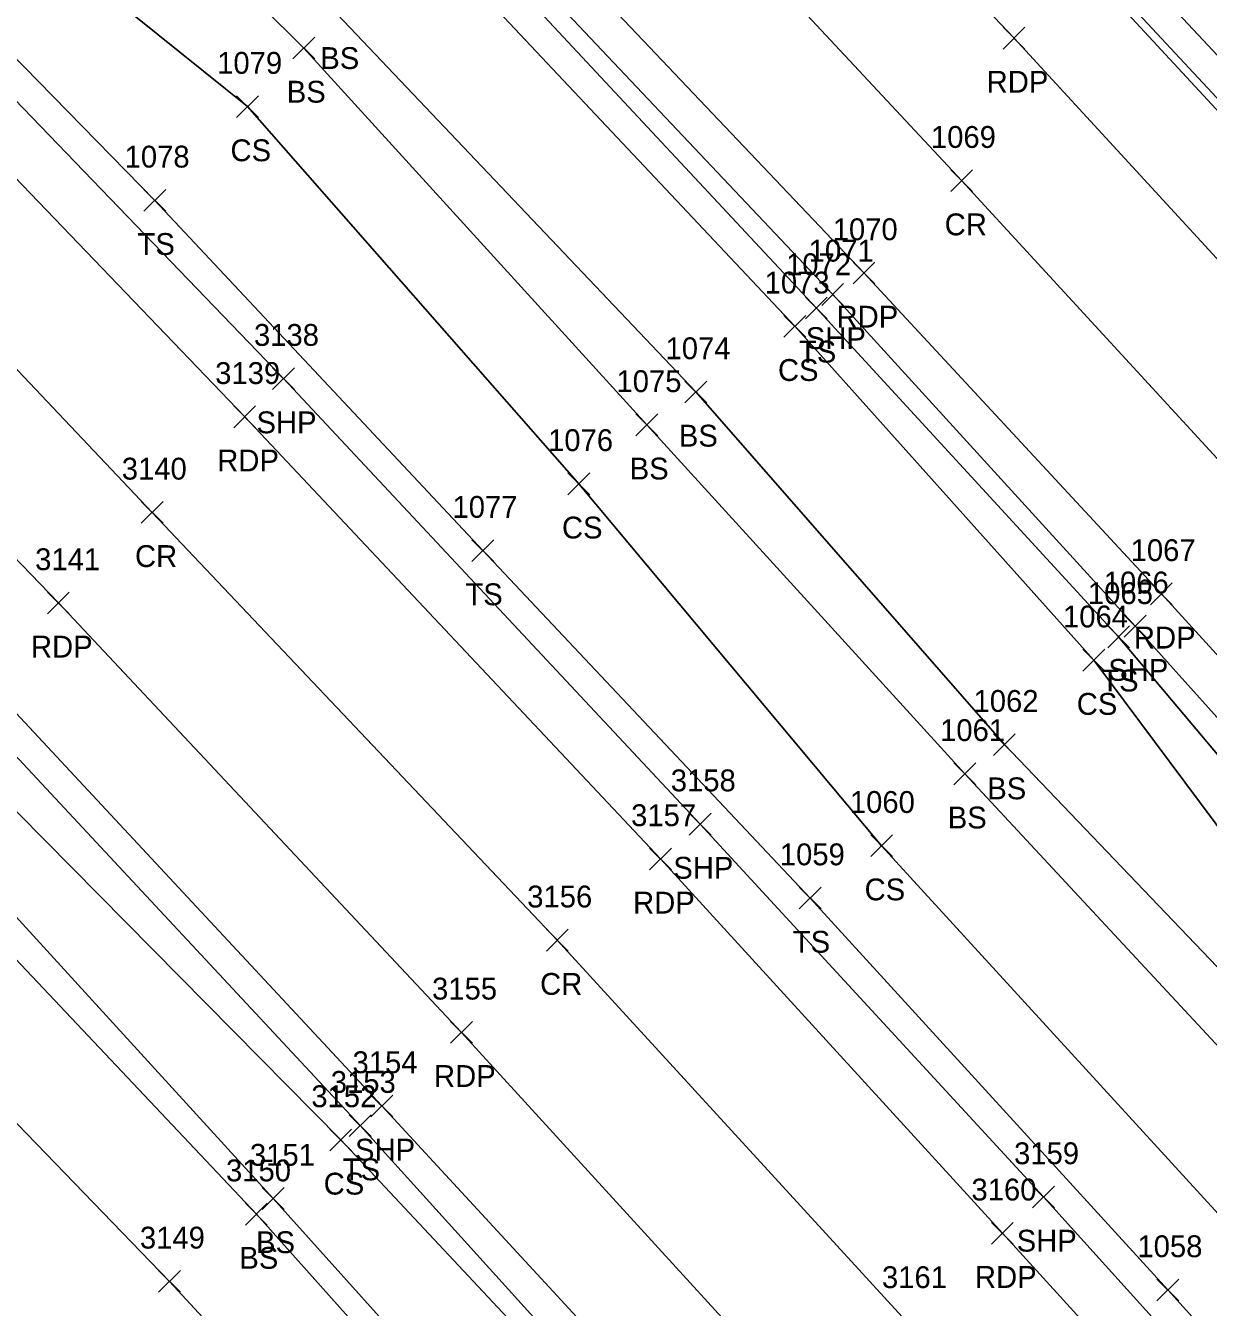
# Model space of a CAD drawing. Extents: x 1647574 to 1652703, y 212895 to 228670.
# Drawn here: x 1649906.5 to 1650014.7, y 226147.3 to 226264.6 of the extents above; entities that cross this region are included whole.
import ezdxf

# ---------------------------------------------------------------- set-up
doc = ezdxf.new("R2010")
doc.units = 0
for name, color, linetype in [('L_A', 7, 'Continuous'), ('L_I', 7, 'Continuous'), ('L_TIC', 7, 'Continuous'), ('LAWA', 7, 'Continuous'), ('LELB', 7, 'Continuous'), ('P_A', 7, 'Continuous'), ('P_I', 7, 'Continuous'), ('P_TIC', 7, 'Continuous'), ('PET', 7, 'Continuous'), ('PRC', 7, 'Continuous'), ('PSP', 7, 'Continuous'), ('RGR', 7, 'Continuous')]:
    doc.layers.add(name, color=color, linetype=linetype)

msp = doc.modelspace()

# ---------------------------------------------------------------- linework, layer by layer
at = {"layer": 'L_TIC'}
for points in [[(1649930.94, 226261.56), (1649932.94, 226263.56)], [(1649932.94, 226261.56), (1649930.94, 226263.56)], [(1649925.78, 226256.2), (1649927.78, 226258.2)], [(1649927.78, 226256.2), (1649925.78, 226258.2)], [(1649917.31, 226247.62), (1649919.31, 226249.62)], [(1649919.31, 226247.62), (1649917.31, 226249.62)], [(1649977.85, 226237.77), (1649979.85, 226239.77)], [(1649979.85, 226237.77), (1649977.85, 226239.77)], [(1649975.89, 226236.09), (1649977.89, 226238.09)], [(1649977.89, 226236.09), (1649975.89, 226238.09)], [(1649966.82, 226230.08), (1649968.82, 226232.08)], [(1649968.82, 226230.08), (1649966.82, 226232.08)], [(1649962.33, 226227.07), (1649964.33, 226229.07)], [(1649964.33, 226227.07), (1649962.33, 226229.07)], [(1649956.12, 226221.67), (1649958.12, 226223.67)], [(1649958.12, 226221.67), (1649956.12, 226223.67)], [(1649947.32, 226215.56), (1649949.32, 226217.56)], [(1649949.32, 226215.56), (1649947.32, 226217.56)], [(1650005.52, 226207.67), (1650007.52, 226209.67)], [(1650007.52, 226207.67), (1650005.52, 226209.67)], [(1650003.25, 226205.53), (1650005.25, 226207.53)], [(1650005.25, 226205.53), (1650003.25, 226207.53)], [(1649995.06, 226197.8), (1649997.06, 226199.8)], [(1649997.06, 226197.8), (1649995.06, 226199.8)], [(1649991.44, 226195.13), (1649993.44, 226197.13)], [(1649993.44, 226195.13), (1649991.44, 226197.13)], [(1649983.83, 226188.55), (1649985.83, 226190.55)], [(1649985.83, 226188.55), (1649983.83, 226190.55)], [(1649977.29, 226183.76), (1649979.29, 226185.76)], [(1649979.29, 226183.76), (1649977.29, 226185.76)], [(1649936.1, 226162.93), (1649938.1, 226164.93)], [(1649938.1, 226162.93), (1649936.1, 226164.93)], [(1649934.32, 226161.62), (1649936.32, 226163.62)], [(1649936.32, 226161.62), (1649934.32, 226163.62)], [(1649928.13, 226156.26), (1649930.13, 226158.26)], [(1649930.13, 226156.26), (1649928.13, 226158.26)], [(1649926.6, 226154.83), (1649928.6, 226156.83)], [(1649928.6, 226154.83), (1649926.6, 226156.83)], [(1649918.64, 226148.68), (1649920.64, 226150.68)], [(1649920.64, 226148.68), (1649918.64, 226150.68)], [(1650010.02, 226147.89), (1650012.02, 226149.89)], [(1650012.02, 226147.89), (1650010.02, 226149.89)]]:
    msp.add_lwpolyline(points, dxfattribs=at)
at = {"layer": 'LAWA'}
msp.add_lwpolyline([(1649564.01, 226501.21), (1649600.78, 226471.1), (1649629.15, 226441.1), (1649657.11, 226422.45), (1649662.3, 226420.26), (1649668.81, 226414.71), (1649676.02, 226404.08), (1649707.48, 226367.52), (1649746.55, 226330.39), (1649779.45, 226297), (1649815.18, 226260.26), (1649850.99, 226223.94), (1649889.13, 226181.22), (1649919.64, 226149.68), (1649954.03, 226112.54), (1649976.77, 226080.57), (1650010.23, 226040.33), (1650031.5, 226013.99), (1650047.73, 225988.88)], dxfattribs=at)
at = {"layer": 'LELB'}
for points in [[(1650213.15, 226037.1), (1650185.87, 226070.33), (1650156.97, 226103.72), (1650126.82, 226139.03), (1650097.45, 226172.49), (1650065.12, 226208.19), (1650039.15, 226236.7), (1650005.62, 226272.51), (1649977.06, 226302.34), (1649946.85, 226333.69), (1649915.81, 226365.02), (1649884.88, 226395.87), (1649852.74, 226426.8), (1649817.4, 226461.44), (1649778.8, 226498.35), (1649747.79, 226526.99), (1649716.78, 226556.99), (1649685.05, 226589.65), (1649647.22, 226623.29), (1649611.68, 226660.43), (1649573.8, 226694.76)], [(1650145.31, 225996.12), (1650155.22, 226000.73), (1650160.97, 226007.39), (1650165.06, 226014.73), (1650162.63, 226023.17), (1650152.14, 226036.38), (1650125.52, 226068.74), (1650101.36, 226098.15), (1650073.79, 226131.47), (1650039.14, 226169.85), (1650006.52, 226208.67), (1649978.85, 226238.77), (1649944.11, 226276), (1649910.77, 226309.61), (1649879.19, 226341.22), (1649849.26, 226371.24), (1649815.2, 226404.44), (1649786.47, 226431.97), (1649749.39, 226466.79), (1649718.31, 226495.58), (1649694.54, 226518.32), (1649659.53, 226550.77), (1649625.91, 226582.74), (1649593.12, 226613.01)], [(1650145.31, 225996.12), (1650126.11, 226017.39), (1650101.66, 226047.08), (1650074.02, 226078.27), (1650048.35, 226107.52), (1650011.02, 226148.89), (1649978.29, 226184.76), (1649948.32, 226216.56), (1649918.31, 226248.62), (1649881.09, 226286.67), (1649854.51, 226315.1), (1649822.53, 226345.57), (1649790.94, 226377.4), (1649759.46, 226406.66), (1649722.98, 226440.72), (1649699.36, 226464.18), (1649670.41, 226492.35), (1649633.05, 226526.99), (1649601.72, 226556.3), (1649565.56, 226590.44)], [(1649576.43, 226518.4), (1649614.41, 226482.98), (1649642.41, 226455.9), (1649685.38, 226415.67), (1649721.92, 226380.74), (1649759.16, 226344.82), (1649794.41, 226310.27), (1649829.09, 226276.12), (1649866.9, 226238.21), (1649900.81, 226202.84), (1649937.1, 226163.93), (1649969.44, 226128.19), (1649998.01, 226097.17), (1650029.45, 226060.68), (1650045.36, 226034.05), (1650069.99, 226009.77), (1650092.51, 225984.63), (1650111.94, 225960.02)], [(1649572.06, 226513.32), (1649610.08, 226478.23), (1649638.08, 226450.58), (1649682.17, 226412.39), (1649718, 226377.59), (1649756, 226340.45), (1649789.26, 226306.39), (1649824.84, 226270.98), (1649865.01, 226237.13), (1649898.41, 226199.96), (1649935.32, 226162.62), (1649968.54, 226127.19), (1649995.98, 226095.51), (1650026.38, 226057.31)], [(1649570.19, 226510.51), (1649608.23, 226476.35), (1649636.57, 226449.06), (1649663.19, 226421.28), (1649670.48, 226414.78), (1649679.22, 226408.18), (1649715.79, 226375.57), (1649754.34, 226338.61), (1649788.1, 226305.21), (1649822.67, 226268.96), (1649860.5, 226231.77), (1649895.97, 226193.57), (1649929.13, 226157.26), (1649962.02, 226120.66), (1649988.9, 226089.08), (1650019.8, 226051.49), (1650041.89, 226022.86), (1650059.37, 225999.62), (1650079.66, 225974.03), (1650096.25, 225946.36)], [(1650034.79, 226165.59), (1650004.25, 226206.53), (1649976.89, 226237.09), (1649942.39, 226273.76), (1649905.43, 226305.34), (1649874.8, 226336.52), (1649843.44, 226365.42), (1649812.48, 226401.05), (1649784.9, 226430.14), (1649744.52, 226461.95), (1649720.63, 226485.58), (1649711.56, 226477.85), (1649711.58, 226477.78), (1649705.42, 226471.73), (1649700.93, 226467.69), (1649709.73, 226458.24)], [(1650148.97, 226010.88), (1650139.27, 226026.59), (1650113.43, 226057), (1650088.3, 226087.98), (1650061.28, 226120.08), (1650026.24, 226159.75), (1649992.44, 226196.13), (1649963.33, 226228.07), (1649931.94, 226262.56), (1649896.29, 226297.95), (1649867.38, 226328.16), (1649836.11, 226358.29), (1649802.88, 226390.85), (1649773.49, 226418.93), (1649757.57, 226433.02), (1649733.38, 226449.67), (1649721.38, 226464.7), (1649717.89, 226468.09), (1649721.1, 226472.27), (1649725.43, 226467.47)], [(1650148.97, 226010.88), (1650154.49, 226019.63), (1650146.18, 226030.47), (1650117.14, 226060.39), (1650092.92, 226091.65), (1650065.04, 226122.85), (1650030.31, 226163.04), (1649996.06, 226198.8), (1649967.82, 226231.08), (1649935.01, 226265.64), (1649900.92, 226301.66), (1649869, 226330.3), (1649837.58, 226359.92), (1649804, 226392.67), (1649775.11, 226420.09), (1649758.52, 226434.35), (1649738.4, 226455.19), (1649725.43, 226467.47)], [(1650055.12, 226113.82), (1650017.96, 226153.32), (1649984.83, 226189.55), (1649957.12, 226222.67), (1649926.78, 226257.2), (1649885.72, 226290.18), (1649859.03, 226319.45), (1649828.58, 226351.31), (1649795.6, 226382.64), (1649764.56, 226410.62), (1649728.45, 226444.97), (1649709.73, 226458.24)], [(1649668.81, 226414.71), (1649677.68, 226406.85), (1649713.8, 226373.3), (1649752.12, 226335.89), (1649786.09, 226302.81), (1649821.42, 226267.05), (1649857.98, 226229.57), (1649894.19, 226191.19), (1649927.6, 226155.83), (1649960.21, 226119.33), (1649987.22, 226087.32), (1650018.26, 226049.98), (1650039.74, 226020.41), (1650056.73, 225997.13), (1650074.38, 225969.86), (1650089, 225939.93)]]:
    msp.add_lwpolyline(points, dxfattribs=at)
at = {"layer": 'P_TIC'}
for points in [[(1649995.95, 226262.47), (1649997.95, 226264.47)], [(1649997.95, 226262.47), (1649995.95, 226264.47)], [(1649991.16, 226249.42), (1649993.16, 226251.42)], [(1649993.16, 226249.42), (1649991.16, 226251.42)], [(1649982.21, 226240.97), (1649984.21, 226242.97)], [(1649984.21, 226240.97), (1649982.21, 226242.97)], [(1649979.35, 226239.01), (1649981.35, 226241.01)], [(1649981.35, 226239.01), (1649979.35, 226241.01)], [(1649929.08, 226231.3), (1649931.08, 226233.3)], [(1649931.08, 226231.3), (1649929.08, 226233.3)], [(1649925.53, 226227.81), (1649927.53, 226229.81)], [(1649927.53, 226227.81), (1649925.53, 226229.81)], [(1649917.06, 226219.06), (1649919.06, 226221.06)], [(1649919.06, 226219.06), (1649917.06, 226221.06)], [(1650009.43, 226211.6), (1650011.43, 226213.6)], [(1650011.43, 226211.6), (1650009.43, 226213.6)], [(1649908.48, 226210.77), (1649910.48, 226212.77)], [(1649910.48, 226210.77), (1649908.48, 226212.77)], [(1650007.03, 226208.64), (1650009.03, 226210.64)], [(1650009.03, 226208.64), (1650007.03, 226210.64)], [(1649967.22, 226190.53), (1649969.22, 226192.53)], [(1649969.22, 226190.53), (1649967.22, 226192.53)], [(1649963.59, 226187.34), (1649965.59, 226189.34)], [(1649965.59, 226187.34), (1649963.59, 226189.34)], [(1649954.14, 226179.9), (1649956.14, 226181.9)], [(1649956.14, 226179.9), (1649954.14, 226181.9)], [(1649945.37, 226171.47), (1649947.37, 226173.47)], [(1649947.37, 226171.47), (1649945.37, 226173.47)], [(1649938.09, 226164.73), (1649940.09, 226166.73)], [(1649940.09, 226164.73), (1649938.09, 226166.73)], [(1649998.65, 226156.4), (1650000.65, 226158.4)], [(1650000.65, 226156.4), (1649998.65, 226158.4)], [(1649994.88, 226153.08), (1649996.88, 226155.08)], [(1649996.88, 226153.08), (1649994.88, 226155.08)]]:
    msp.add_lwpolyline(points, dxfattribs=at)
at = {"layer": 'PET'}
for points in [[(1650203.46, 226029.18), (1650176.21, 226061.89), (1650147.53, 226095.79), (1650117.29, 226130.73), (1650087.4, 226164.52), (1650055.9, 226199.34), (1650029.44, 226228.14), (1649996.95, 226263.47), (1649968.15, 226293.72), (1649938.19, 226324.52), (1649906.65, 226356.13), (1649876.52, 226386.27), (1649843.75, 226418.81), (1649809.66, 226451.94), (1649770.32, 226489.71), (1649739.98, 226518.42), (1649716.1, 226541.38), (1649682.51, 226572.89), (1649648.23, 226605.38), (1649615.14, 226636.4), (1649578.52, 226671.42)], [(1650180.12, 226018.51), (1650160.2, 226042.42), (1650132.53, 226074.87), (1650108.24, 226103.36), (1650079.8, 226135.84), (1650045.18, 226174.49), (1650010.43, 226212.6), (1649983.21, 226241.97), (1649947.38, 226279.71), (1649914.98, 226313), (1649883.03, 226345), (1649852.9, 226374.89), (1649819.24, 226408.27), (1649790.46, 226435.99), (1649753.36, 226471.35), (1649722.68, 226500.42), (1649698.76, 226522.75), (1649664.62, 226555.39), (1649630.41, 226587.57), (1649598.45, 226617.55), (1649561.34, 226652.9)], [(1649568.76, 226578.15), (1649602.84, 226545.72), (1649639.6, 226511.14), (1649669.58, 226482.71), (1649710.56, 226443.02), (1649749.16, 226406.1), (1649783.82, 226372.91), (1649821.53, 226335.91), (1649854.36, 226303.39), (1649893.84, 226262.84), (1649926.53, 226228.81), (1649964.59, 226188.34), (1649995.88, 226154.08), (1650026.58, 226120.39), (1650056.63, 226086.43), (1650078.17, 226061.47), (1650102.87, 226032.97), (1650121.07, 226011.5), (1650140.46, 225987.82)], [(1649585.69, 226528.77), (1649624.3, 226492.34), (1649652.1, 226465.47), (1649694.18, 226424.93), (1649731.2, 226389.82), (1649767.06, 226355.29), (1649804.34, 226318.78), (1649837.23, 226285.73), (1649875.09, 226247.37), (1649909.48, 226211.77), (1649946.37, 226172.47), (1649978.25, 226137.54), (1650007.65, 226104.95), (1650038.73, 226069.71), (1650059.42, 226046.29), (1650084.31, 226017.14), (1650102.55, 225995.44), (1650123.3, 225970.1)]]:
    msp.add_lwpolyline(points, dxfattribs=at)
at = {"layer": 'PRC'}
for points in [[(1650190.29, 226025.07), (1650169.4, 226050.68), (1650141.73, 226083.3), (1650117.9, 226111.09), (1650088.92, 226144.57), (1650053.94, 226182.93), (1650019.72, 226220.45), (1649992.16, 226250.42), (1649956.56, 226288.56), (1649923.88, 226321.79), (1649891.54, 226354.39), (1649861.68, 226384.4), (1649827.7, 226416.9), (1649798.54, 226445.37), (1649761.96, 226480.16), (1649731.42, 226509.46), (1649707.37, 226531.84), (1649673.7, 226564), (1649639.62, 226596.15), (1649606.75, 226626.95), (1649570.25, 226661.64)], [(1649559.91, 226569.96), (1649593.92, 226537.25), (1649631.94, 226502.23), (1649660.46, 226474.34), (1649702.15, 226434.36), (1649740.4, 226397.48), (1649775.04, 226364.12), (1649813.32, 226327.22), (1649846.03, 226294.55), (1649884.93, 226255.04), (1649918.06, 226220.06), (1649955.14, 226180.9), (1649987.04, 226146.06), (1650016.78, 226113.16), (1650047.62, 226077.89), (1650069.26, 226053.4), (1650093.06, 226025.47), (1650111.86, 226003.86), (1650131.21, 225979.86)]]:
    msp.add_lwpolyline(points, dxfattribs=at)
at = {"layer": 'PSP'}
for points in [[(1650209.98, 226034.8), (1650182.89, 226067.68), (1650153.83, 226101.81), (1650124.05, 226136.25), (1650094.35, 226170.32), (1650062.83, 226205.52), (1650036.19, 226234.57), (1650003.11, 226270.29), (1649975.25, 226299.75), (1649944.68, 226331.46), (1649913.77, 226362.55), (1649883.23, 226393.29), (1649850.54, 226425.12), (1649815.25, 226459.11), (1649776.56, 226495.81), (1649746.09, 226524.83), (1649714.65, 226554.46), (1649681.67, 226585.65), (1649644.69, 226620.23), (1649606.95, 226655.87), (1649570.92, 226690.01)], [(1650176.78, 226014.91), (1650174.69, 226018.89), (1650157.03, 226040.39), (1650129.97, 226072.67), (1650105.28, 226101.15), (1650076.93, 226133.75), (1650041.79, 226172.07), (1650008.03, 226209.64), (1649980.35, 226240.01), (1649944.97, 226277.48), (1649912.15, 226310.56), (1649880.37, 226342.42), (1649850.35, 226372.48), (1649816.61, 226405.58), (1649787.78, 226433.35), (1649750.91, 226468.71), (1649720.44, 226497.53), (1649696.48, 226520.16), (1649661.7, 226552.53), (1649627.77, 226584.84), (1649595.64, 226615.02), (1649558.33, 226650.15)], [(1649571.18, 226581.28), (1649605.62, 226548.46), (1649642.47, 226514.36), (1649673.51, 226485.11), (1649713.05, 226446.56), (1649753.13, 226408.58), (1649786.75, 226376.31), (1649825.02, 226339.17), (1649858.01, 226306.81), (1649897.5, 226266.11), (1649930.08, 226232.3), (1649968.22, 226191.53), (1649999.65, 226157.4), (1650029.99, 226123.79), (1650060.42, 226089.05), (1650081.82, 226064.3), (1650106.87, 226035.38), (1650124.34, 226014.45), (1650143.68, 225990.93)], [(1649578.75, 226520.79), (1649616.88, 226484.95), (1649644.67, 226458.4), (1649687.66, 226417.66), (1649724.18, 226382.77), (1649761.14, 226347.64), (1649797.11, 226312.71), (1649831.3, 226278.59), (1649868.9, 226240.31), (1649902.65, 226204.83), (1649939.09, 226165.73), (1649971.52, 226130.61), (1650000.21, 226098.9), (1650032.08, 226063.05), (1650053.34, 226038.39), (1650075.13, 226014.23), (1650096.57, 225988.88), (1650117.58, 225964.05)]]:
    msp.add_lwpolyline(points, dxfattribs=at)
at = {"layer": 'RGR'}
msp.add_lwpolyline([(1650210.88, 226035.34), (1650183.47, 226068.36), (1650154.6, 226102.18), (1650124.72, 226137.1), (1650095.1, 226170.93), (1650063.42, 226206.14), (1650036.95, 226235.01), (1650003.69, 226270.69), (1649975.87, 226300.38), (1649945.2, 226332.04), (1649914.34, 226363.19), (1649883.95, 226393.7), (1649851.2, 226425.71), (1649815.73, 226459.46), (1649777.08, 226496.44), (1649746.45, 226525.34), (1649715.22, 226555.07), (1649682.27, 226586.18), (1649645.22, 226621.05), (1649607.54, 226656.38), (1649571.29, 226690.65)], dxfattribs=at)

# ---------------------------------------------------------------- texts
at = {"layer": 'L_A'}
for s, p in [('BS', (1649933.45, 226260.64)), ('BS', (1649930.38, 226257.56)), ('CS', (1649925.23, 226252.2)), ('TS', (1649916.72, 226243.62)), ('TS', (1649977.26, 226233.77)), ('CS', (1649975.34, 226232.09)), ('BS', (1649966.27, 226226.08)), ('BS', (1649961.77, 226223.07)), ('CS', (1649955.57, 226217.67)), ('TS', (1649946.73, 226211.56)), ('TS', (1650004.93, 226203.67)), ('CS', (1650002.69, 226201.53)), ('BS', (1649994.5, 226193.8)), ('BS', (1649990.88, 226191.13)), ('CS', (1649983.27, 226184.55)), ('TS', (1649976.7, 226179.76)), ('TS', (1649935.51, 226158.93)), ('CS', (1649933.76, 226157.62)), ('BS', (1649927.57, 226152.26)), ('BS', (1649926.04, 226150.83))]:
    msp.add_text(s, height=2, dxfattribs=at).set_placement(p)
at = {"layer": 'L_I'}
for s, p in [('1079', (1649924.01, 226260.2)), ('1078', (1649915.54, 226251.62)), ('1072', (1649976.08, 226241.77)), ('1073', (1649974.12, 226240.09)), ('1074', (1649965.05, 226234.08)), ('1075', (1649960.56, 226231.07)), ('1076', (1649954.3, 226225.67)), ('1077', (1649945.55, 226219.56)), ('1065', (1650003.71, 226211.67)), ('1064', (1650001.43, 226209.53)), ('1062', (1649993.24, 226201.8)), ('1061', (1649990.18, 226199.13)), ('1060', (1649981.92, 226192.55)), ('1059', (1649975.51, 226187.76)), ('3153', (1649934.41, 226166.93)), ('3152', (1649932.63, 226165.62)), ('3151', (1649927.01, 226160.26)), ('3150', (1649924.82, 226158.83)), ('3149', (1649916.94, 226152.68)), ('1058', (1650008.24, 226151.89))]:
    msp.add_text(s, height=2, dxfattribs=at).set_placement(p)
at = {"layer": 'P_A'}
for s, p in [('RDP', (1649994.44, 226258.47)), ('CR', (1649990.6, 226245.42)), ('RDP', (1649980.7, 226236.97)), ('SHP', (1649977.89, 226235.01)), ('SHP', (1649927.61, 226227.3)), ('RDP', (1649924.02, 226223.81)), ('CR', (1649916.49, 226215.06)), ('RDP', (1650007.92, 226207.6)), ('RDP', (1649906.97, 226206.77)), ('SHP', (1650005.57, 226204.64)), ('SHP', (1649965.76, 226186.53)), ('RDP', (1649962.08, 226183.34)), ('CR', (1649953.57, 226175.9)), ('RDP', (1649943.86, 226167.47)), ('SHP', (1649936.63, 226160.73)), ('SHP', (1649997.19, 226152.4)), ('RDP', (1649993.37, 226149.08))]:
    msp.add_text(s, height=2, dxfattribs=at).set_placement(p)
at = {"layer": 'P_I'}
for s, p in [('1069', (1649989.34, 226253.42)), ('1070', (1649980.35, 226244.97)), ('1071', (1649978.15, 226243.01)), ('3138', (1649927.38, 226235.3)), ('3139', (1649923.83, 226231.81)), ('3140', (1649915.28, 226223.06)), ('1067', (1650007.62, 226215.6)), ('3141', (1649907.35, 226214.77)), ('1066', (1650005.16, 226212.64)), ('3158', (1649965.53, 226194.53)), ('3157', (1649961.9, 226191.34)), ('3156', (1649952.39, 226183.9)), ('3155', (1649943.68, 226175.47)), ('3154', (1649936.4, 226168.73)), ('3159', (1649996.95, 226160.4)), ('3160', (1649993.05, 226157.08)), ('3161', (1649984.86, 226149.06))]:
    msp.add_text(s, height=2, dxfattribs=at).set_placement(p)

doc.saveas('drawing.dxf')
